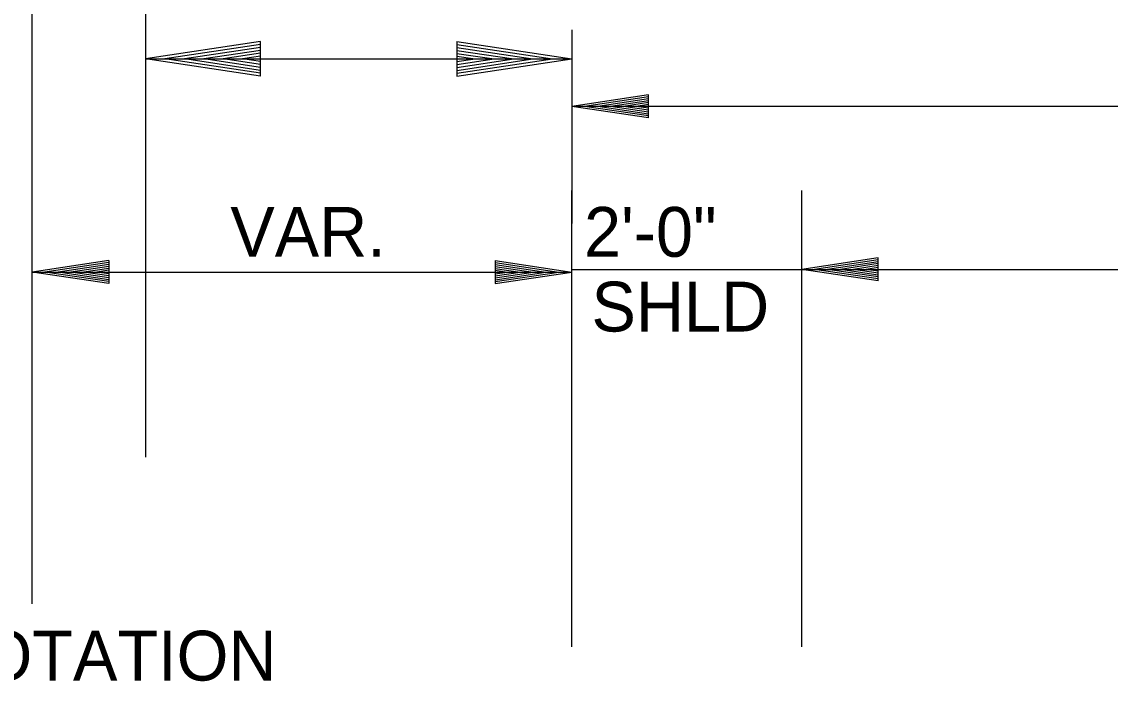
# Model space of a CAD drawing. Extents: x 1373719 to 1374161, y 379835 to 380167.
# Drawn here: x 1373935.35 to 1373949.55, y 379925.38 to 379933.99 of the extents above; entities that cross this region are included whole.
import ezdxf

# ---------------------------------------------------------------- set-up
doc = ezdxf.new("R2010")
doc.units = 0
doc.layers.add('GREEN_TXT', color=7, linetype='Continuous')
doc.layers.add('Text 1', color=7, linetype='Continuous')

msp = doc.modelspace()

# ---------------------------------------------------------------- linework, layer by layer
at = {"layer": 'GREEN_TXT'}
for p, q in [((1373935.483, 379926.394), (1373935.483, 379937.543)), ((1373942.525, 379933.884), (1373942.525, 379931.358)), ((1373943.525, 379933.034), (1373942.525, 379932.884)), ((1373943.525, 379933.009), (1373942.692, 379932.884)), ((1373943.525, 379932.734), (1373943.525, 379933.034)), ((1373981.525, 379932.884), (1373942.525, 379932.884)), ((1373943.525, 379932.734), (1373942.525, 379932.884)), ((1373943.525, 379932.759), (1373942.692, 379932.884)), ((1373943.525, 379932.983), (1373942.864, 379932.884)), ((1373943.525, 379932.784), (1373942.864, 379932.884)), ((1373943.525, 379932.958), (1373943.03, 379932.884)), ((1373943.525, 379932.809), (1373943.03, 379932.884)), ((1373943.525, 379932.933), (1373943.2, 379932.884)), ((1373943.525, 379932.835), (1373943.2, 379932.884)), ((1373943.525, 379932.907), (1373943.367, 379932.884)), ((1373943.525, 379932.86), (1373943.367, 379932.884)), ((1373942.525, 379925.834), (1373942.525, 379931.786)), ((1373945.525, 379925.834), (1373945.525, 379931.786)), ((1373936.483, 379930.873), (1373935.483, 379930.723)), ((1373936.483, 379930.873), (1373936.483, 379930.573)), ((1373941.525, 379930.873), (1373942.525, 379930.723)), ((1373941.525, 379930.873), (1373941.525, 379930.573)), ((1373946.525, 379930.908), (1373945.525, 379930.758)), ((1373946.525, 379930.883), (1373945.692, 379930.758)), ((1373946.525, 379930.608), (1373946.525, 379930.908)), ((1373936.483, 379930.848), (1373935.65, 379930.723)), ((1373936.483, 379930.822), (1373935.822, 379930.723)), ((1373936.483, 379930.797), (1373935.988, 379930.723)), ((1373936.483, 379930.771), (1373936.158, 379930.723)), ((1373936.483, 379930.746), (1373936.325, 379930.723)), ((1373941.525, 379930.848), (1373942.358, 379930.723)), ((1373941.525, 379930.822), (1373942.186, 379930.723)), ((1373941.525, 379930.797), (1373942.019, 379930.723)), ((1373941.525, 379930.771), (1373941.85, 379930.723)), ((1373941.525, 379930.746), (1373941.683, 379930.723)), ((1373942.525, 379930.758), (1373945.525, 379930.758)), ((1373945.525, 379930.758), (1373962.025, 379930.758)), ((1373946.525, 379930.608), (1373945.525, 379930.758)), ((1373946.525, 379930.633), (1373945.692, 379930.758)), ((1373946.525, 379930.858), (1373945.864, 379930.758)), ((1373946.525, 379930.659), (1373945.864, 379930.758)), ((1373946.525, 379930.833), (1373946.03, 379930.758)), ((1373946.525, 379930.684), (1373946.03, 379930.758)), ((1373946.525, 379930.807), (1373946.2, 379930.758)), ((1373946.525, 379930.71), (1373946.2, 379930.758)), ((1373946.525, 379930.782), (1373946.367, 379930.758)), ((1373946.525, 379930.735), (1373946.367, 379930.758)), ((1373935.483, 379930.723), (1373942.525, 379930.723)), ((1373936.483, 379930.573), (1373935.483, 379930.723)), ((1373936.483, 379930.598), (1373935.65, 379930.723)), ((1373936.483, 379930.623), (1373935.822, 379930.723)), ((1373936.483, 379930.648), (1373935.988, 379930.723)), ((1373936.483, 379930.674), (1373936.158, 379930.723)), ((1373936.483, 379930.699), (1373936.325, 379930.723)), ((1373941.525, 379930.573), (1373942.525, 379930.723)), ((1373941.525, 379930.674), (1373941.85, 379930.723)), ((1373941.525, 379930.623), (1373942.186, 379930.723)), ((1373941.525, 379930.598), (1373942.358, 379930.723)), ((1373941.525, 379930.648), (1373942.019, 379930.723)), ((1373941.525, 379930.699), (1373941.683, 379930.723))]:
    msp.add_line(p, q, dxfattribs=at)
at = {"layer": 'Text 1'}
for p, q in [((1373936.963, 379949.648), (1373936.963, 379928.307)), ((1373938.463, 379933.729), (1373936.963, 379933.504)), ((1373938.463, 379933.279), (1373938.463, 379933.729)), ((1373941.025, 379933.729), (1373942.525, 379933.504)), ((1373941.025, 379933.729), (1373941.025, 379933.279)), ((1373938.463, 379933.691), (1373937.213, 379933.504)), ((1373938.463, 379933.654), (1373937.471, 379933.504)), ((1373938.463, 379933.615), (1373937.722, 379933.504)), ((1373938.463, 379933.577), (1373937.975, 379933.504)), ((1373941.025, 379933.691), (1373942.274, 379933.504)), ((1373941.025, 379933.652), (1373942.016, 379933.504)), ((1373941.025, 379933.615), (1373941.767, 379933.504)), ((1373941.025, 379933.576), (1373941.512, 379933.504)), ((1373938.463, 379933.279), (1373936.963, 379933.504)), ((1373936.963, 379933.504), (1373942.525, 379933.504)), ((1373938.463, 379933.316), (1373937.213, 379933.504)), ((1373938.463, 379933.354), (1373937.471, 379933.504)), ((1373938.463, 379933.393), (1373937.722, 379933.504)), ((1373938.463, 379933.432), (1373937.975, 379933.504)), ((1373938.463, 379933.54), (1373938.226, 379933.504)), ((1373938.463, 379933.468), (1373938.226, 379933.504)), ((1373941.025, 379933.538), (1373941.262, 379933.504)), ((1373941.025, 379933.279), (1373942.525, 379933.504)), ((1373941.025, 379933.43), (1373941.512, 379933.504)), ((1373941.025, 379933.354), (1373942.016, 379933.504)), ((1373941.025, 379933.316), (1373942.274, 379933.504)), ((1373941.025, 379933.391), (1373941.767, 379933.504)), ((1373941.025, 379933.468), (1373941.262, 379933.504))]:
    msp.add_line(p, q, dxfattribs=at)

# ---------------------------------------------------------------- texts
at = {"layer": 'GREEN_TXT'}
for s, p in [('2\'-0"', (1373942.685, 379930.922)), ('VAR.', (1373938.069, 379930.922)), ('SHLD', (1373942.782, 379929.947)), ('POINT OF SUPER ROTATION', (1373926.599, 379925.393))]:
    msp.add_text(s, height=0.65, dxfattribs=at).set_placement(p)

doc.saveas('drawing.dxf')
